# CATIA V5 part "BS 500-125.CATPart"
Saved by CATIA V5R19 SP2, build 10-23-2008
Part number: BS 500-125
Bounding box of the stored display mesh (mm): x -18.951 to 18.951, y -18.952 to 18.952, z 0 to 280
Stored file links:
  C:\Users\Bora\Desktop\3D Katı model\BS serisi\BS 500\BS 500-125.CATPart
  C:\Program Files\Dassault Systemes\B19\intel_a\reffiles\standard\MetricThickPitch.txt
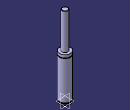
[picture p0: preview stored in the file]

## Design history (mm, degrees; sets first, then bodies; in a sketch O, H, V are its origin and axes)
Body1 (main body)
  Sketch1 on yz-plane, origin (0, 0, 0), H (0, 1, 0), V (0, 0, 1)
    point P1 (10, 279)
    point P3 (10, 279)
    point P5 (19, 144.5)
    point P6 (19, 142.5)
    point P9 (19, 144.5)
    point P14 (19, 142.5)
    line L1 (10, 279) -> (10, 154)
    arc A1 centre (9, 279) radius 1 from (10, 279) to (9, 280) ccw
    arc A2 centre (19, 143.5) radius 1 from (19, 144.5) to (19, 142.5) ccw
    line L2 (19, 0) -> (19, 4)
    line L3 (19, 144.5) -> (19, 154)
    line L4 (17, 7.5) -> (17, 4)
    line L5 (19, 7.5) -> (19, 142.5)
    line L6 (9, 280) -> (0, 280)
    point P15 (0, 280)
    line L7 (10, 154) -> (19, 154)
    line L8 (0, 0) -> (19, 0)
    line L9 (17, 7.5) -> (19, 7.5)
    line L10 (17, 4) -> (19, 4)
    coincidence: P15 V, P1 P3, P5 P9, P6 P14
    tangency: L6 A1
    horizontal: L7 H, L8 H, L9 H, L10 H
  Shaft1: profile Sketch1, axis Sketch1.V, angle 360
  Sketch2 on face of Shaft1 from Sketch1.L8, origin (0, 0, 0), H (1, 0, 0), V (0, -1, 0)
    point P1 (0, 0)
  Hole1: placed by Sketch2, at (0, 0, 0) direction (0, 0, 1), diameter 6.647, depth 4, threaded "M8", thread diameter 8, thread depth 4, pitch 1.25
